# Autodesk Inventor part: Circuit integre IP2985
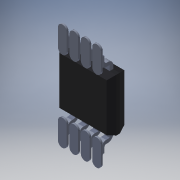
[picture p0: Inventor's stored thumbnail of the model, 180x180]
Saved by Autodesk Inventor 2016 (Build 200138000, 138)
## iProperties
Created: 2018-03
Part Number: Circuit integre IP2985
Material: Générique
Document SubType Name: Modeling
Designer: Bruno
Density: 1 g/cm^3
Appearance: Par défaut
Author: Bruno
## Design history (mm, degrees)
feature "Composite1"
body "Srf1"
